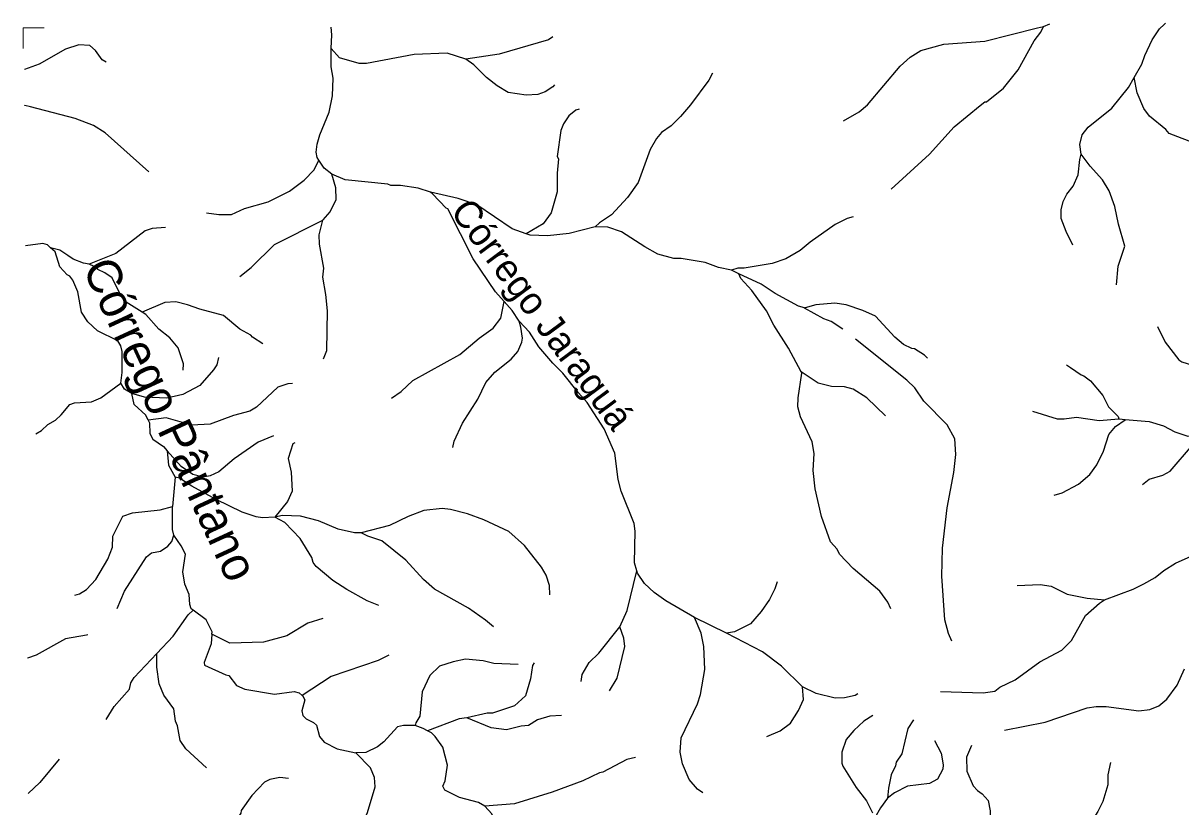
# Model space of a CAD drawing. Extents: x 393 to 446.6, y 8175.5 to 8231.
# Drawn here: x 392.99 to 399.75, y 8226.24 to 8230.82 of the extents above; entities that cross this region are included whole.
import ezdxf
from ezdxf.enums import TextEntityAlignment as Align

# ---------------------------------------------------------------- set-up
doc = ezdxf.new("R2010")
doc.units = 0
doc.header["$LTSCALE"] = 0.064
doc.linetypes.add('LONG_DASHED', pattern=[7.5, 6, -1.5])
doc.layers.add('61', color=7, linetype='Continuous')
for name, color, linetype, lineweight in [('63', 7, 'Continuous', 13), ('7', 7, 'Continuous', 25), ('9', 7, 'LONG_DASHED', 25)]:
    doc.layers.add(name, color=color, linetype=linetype, lineweight=lineweight)

msp = doc.modelspace()

# ---------------------------------------------------------------- linework, layer by layer
at = {"layer": '63'}
msp.add_lwpolyline([(393.1158, 8230.7899), (392.9926, 8230.7899), (392.9926, 8230.6685)], dxfattribs=at)
at = {"layer": '7'}
msp.add_line((398.9443, 8230.7981), (398.9812, 8230.814), dxfattribs=at)
for points in [[(397.7775, 8230.2468), (397.8682, 8230.2997), (397.9166, 8230.3401), (398.1087, 8230.5662), (398.1653, 8230.6178), (398.2283, 8230.6566), (398.3623, 8230.6953), (398.6013, 8230.7115), (398.9092, 8230.789), (398.9443, 8230.7981)], [(398.0551, 8229.8492), (398.2783, 8230.0527), (398.4236, 8230.2125), (398.5738, 8230.3369), (398.6013, 8230.3579), (398.611, 8230.3579), (398.7111, 8230.4386), (398.7966, 8230.5452), (398.8887, 8230.7132), (398.9288, 8230.7645), (398.9443, 8230.7981)], [(399.4726, 8230.5002), (399.5168, 8230.5775), (399.5346, 8230.6292), (399.5782, 8230.7196), (399.6202, 8230.7842), (399.6485, 8230.81), (399.6563, 8230.8171)], [(393.4765, 8230.5902), (393.4544, 8230.603), (393.4146, 8230.6566), (393.3807, 8230.6857), (393.3177, 8230.6905), (393.2402, 8230.6647), (393.0851, 8230.5781), (393.0006, 8230.5457), (393.0005, 8230.5457)], [(399.1639, 8230.0524), (399.1558, 8230.1082), (399.1697, 8230.1657), (399.2036, 8230.2109), (399.3425, 8230.3207), (399.4393, 8230.4419), (399.4726, 8230.5002)], [(399.9445, 8230.105), (399.8964, 8230.0995), (399.8447, 8230.1092), (399.6768, 8230.1722), (399.6573, 8230.1964), (399.5621, 8230.2739), (399.5282, 8230.3191), (399.491, 8230.4096), (399.4726, 8230.5002)], [(393.7252, 8229.9502), (393.4711, 8230.177), (393.4033, 8230.219), (393.2951, 8230.261), (393.0351, 8230.3288), (393.0016, 8230.3375), (393.0015, 8230.3376)], [(399.1152, 8229.5216), (399.076, 8229.6005), (399.047, 8229.6765), (399.047, 8229.7281), (399.0582, 8229.7766), (399.0808, 8229.8186), (399.1164, 8229.8654), (399.1454, 8229.9316), (399.1551, 8230.022), (399.1639, 8230.0524)], [(399.3697, 8229.2906), (399.3796, 8229.3987), (399.4184, 8229.515), (399.3812, 8229.6442), (399.3602, 8229.7475), (399.3263, 8229.8379), (399.2875, 8229.9025), (399.2165, 8229.9816), (399.1639, 8230.0524)], [(399.6087, 8229.0463), (399.6541, 8228.9563), (399.7333, 8228.8529), (399.751, 8228.8416), (399.9658, 8228.7737), (400.032, 8228.735), (400.1143, 8228.6575), (400.1998, 8228.622)], [(399.0775, 8228.824), (399.1009, 8228.8071), (399.1632, 8228.7641), (399.1786, 8228.7584), (399.2181, 8228.7302), (399.2892, 8228.6446), (399.3231, 8228.5784), (399.3796, 8228.5218), (399.3832, 8228.5077), (399.3833, 8228.5073)], [(398.8791, 8228.5536), (399.0237, 8228.5089), (399.0636, 8228.5073), (399.1368, 8228.5186), (399.2691, 8228.4992), (399.3833, 8228.5073)], [(399.0067, 8228.0623), (399.0533, 8228.0763), (399.1471, 8228.1262), (399.2149, 8228.1843), (399.2552, 8228.2393), (399.294, 8228.32), (399.3247, 8228.4169), (399.3634, 8228.4637), (399.4193, 8228.5031), (399.4211, 8228.5043)], [(399.3833, 8228.5073), (399.3848, 8228.5074), (399.4211, 8228.5043)], [(399.4211, 8228.5043), (399.5603, 8228.4926), (399.6438, 8228.4669), (399.7103, 8228.4325), (399.7866, 8228.4064), (399.8461, 8228.4127), (399.8464, 8228.4131)], [(399.5206, 8228.1256), (399.5605, 8228.1569), (399.6396, 8228.1795), (399.6832, 8228.2037), (399.8124, 8228.3539), (399.8458, 8228.412), (399.8464, 8228.4131)], [(399.2989, 8227.4527), (399.4668, 8227.5142), (399.5282, 8227.5449), (399.5944, 8227.582), (399.646, 8227.624), (399.7139, 8227.666), (399.8576, 8227.7306), (399.9642, 8227.7597), (400.2096, 8227.8016), (400.3647, 8227.8049), (400.5862, 8227.7858)], [(398.7908, 8227.5362), (398.9243, 8227.5417), (398.9888, 8227.532), (399.0825, 8227.4851), (399.1988, 8227.4609), (399.2989, 8227.4527)], [(398.3436, 8226.9177), (398.5916, 8226.9087), (398.6594, 8226.9183), (398.6885, 8226.9426), (398.7789, 8226.9862), (398.9226, 8227.0895), (399.0502, 8227.159), (399.1067, 8227.2155), (399.189, 8227.3608), (399.2698, 8227.4335), (399.2989, 8227.4527)], [(393.3697, 8227.247), (393.3614, 8227.2456), (393.2402, 8227.2252), (393.069, 8227.1283), (393.0173, 8227.1124), (393.0171, 8227.1123)], [(398.7159, 8226.6908), (398.9533, 8226.7375), (399.1988, 8226.8215), (399.2504, 8226.8295), (399.3086, 8226.8295), (399.4991, 8226.8037), (399.5637, 8226.8118), (399.617, 8226.8328), (399.6638, 8226.8715), (399.7235, 8226.9539), (399.7672, 8227.0491)], [(397.9481, 8226.7774), (397.8956, 8226.744), (397.8375, 8226.6891), (397.7939, 8226.6374), (397.768, 8226.5631), (397.768, 8226.4985), (397.7729, 8226.4824), (397.8504, 8226.3564), (397.9117, 8226.2789), (397.9459, 8226.2097)], [(398.1849, 8226.7511), (398.1524, 8226.702), (398.1168, 8226.5534), (398.0845, 8226.505), (398.0813, 8226.484), (398.0555, 8226.4307), (398.0393, 8226.3532), (398.0342, 8226.2953)], [(398.3074, 8226.6319), (398.3461, 8226.5567), (398.3591, 8226.4889), (398.3558, 8226.4646), (398.3251, 8226.4065), (398.2783, 8226.3806), (398.1508, 8226.3645), (398.0749, 8226.3257), (398.0342, 8226.2953)], [(398.5237, 8226.6023), (398.4947, 8226.5341), (398.4963, 8226.4533), (398.5334, 8226.3677), (398.5593, 8226.3386), (398.5868, 8226.3209), (398.6206, 8226.2805), (398.6336, 8226.2208), (398.6336, 8226.1336), (398.6513, 8226.1013), (398.6497, 8226.09), (398.6739, 8226.0657), (398.6917, 8226.0318), (398.6982, 8225.9915), (398.682, 8225.9382), (398.6546, 8225.9204), (398.6416, 8225.8849), (398.6449, 8225.8365), (398.6704, 8225.7237)], [(393.2019, 8226.5216), (393.09, 8226.3855), (393.0212, 8226.3227), (393.0209, 8226.3225)], [(399.3353, 8226.502), (399.3182, 8226.4307), (399.3182, 8226.3726), (399.2892, 8226.2757), (399.2617, 8226.2176), (399.2294, 8226.1691), (399.1987, 8226.14), (399.1203, 8226.0969)], [(394.5396, 8226.4097), (394.49, 8226.4162), (394.4319, 8226.4033), (394.4012, 8226.3887), (394.3269, 8226.3112), (394.2639, 8226.2224), (394.2623, 8226.2079), (394.2219, 8226.1465), (393.8893, 8225.9285), (393.8054, 8225.8946), (393.6826, 8225.8623), (393.4889, 8225.7912), (393.481, 8225.7868), (393.3177, 8225.6959), (393.237, 8225.6701), (393.181, 8225.6595), (393.1388, 8225.6505)], [(398.0342, 8226.2953), (397.9935, 8226.2378), (397.9601, 8226.1809)]]:
    msp.add_lwpolyline(points, dxfattribs=at)
at = {"layer": '9'}
for p, q in [((397.1668, 8229.3547), (397.1241, 8229.3749)), ((397.0954, 8227.2574), (396.9083, 8227.3483))]:
    msp.add_line(p, q, dxfattribs=at)
for points in [[(394.7892, 8230.6685), (394.7921, 8230.7491), (394.7899, 8230.7946)], [(396.0821, 8230.7369), (396.0566, 8230.7206), (395.7693, 8230.6353), (395.5744, 8230.6071)], [(394.7181, 8230.0169), (394.7079, 8230.0331), (394.7023, 8230.0642), (394.7075, 8230.1119), (394.7233, 8230.1661), (394.777, 8230.2972), (394.7969, 8230.3938), (394.8015, 8230.4967), (394.7887, 8230.5617), (394.7892, 8230.6685)], [(395.5744, 8230.6071), (395.465, 8230.6412), (395.2729, 8230.6341), (394.9959, 8230.581), (394.9525, 8230.5807), (394.8382, 8230.6141), (394.7892, 8230.6685)], [(396.0922, 8230.4576), (396.0829, 8230.4452), (396.0374, 8230.4154), (395.9937, 8230.4001), (395.9265, 8230.3966), (395.8219, 8230.4129), (395.7567, 8230.451), (395.6951, 8230.4995), (395.6208, 8230.5737), (395.5744, 8230.6071)], [(397.0134, 8230.5247), (396.9913, 8230.4839), (396.8848, 8230.3401), (396.8266, 8230.2723), (396.7717, 8230.2174), (396.7152, 8230.1786), (396.6861, 8230.1447), (396.649, 8230.0802), (396.5796, 8229.888), (396.5166, 8229.7992), (396.4245, 8229.699), (396.3535, 8229.6522), (396.3286, 8229.6288)], [(396.2348, 8230.3146), (396.2169, 8230.3095), (396.1755, 8230.2763), (396.1446, 8230.2304), (396.1288, 8230.1907), (396.1065, 8230.0386), (396.1145, 8230.0247), (396.1064, 8229.9413), (396.1079, 8229.8321), (396.0717, 8229.7108), (396.0266, 8229.6467), (395.9263, 8229.5878)], [(394.0617, 8229.7097), (394.1338, 8229.7005), (394.207, 8229.7015), (394.2828, 8229.7353), (394.4215, 8229.7749), (394.5455, 8229.8376), (394.6323, 8229.9001), (394.6894, 8229.9615), (394.7181, 8230.0169)], [(394.7921, 8229.9358), (394.7476, 8229.97), (394.7181, 8230.0169)], [(394.7401, 8229.6675), (394.7425, 8229.6687), (394.783, 8229.7158), (394.8182, 8229.7879), (394.817, 8229.8554), (394.7921, 8229.9358)], [(395.3693, 8229.8311), (395.296, 8229.854), (395.1934, 8229.8701), (395.1372, 8229.8702), (395.1197, 8229.8766), (394.8705, 8229.9027), (394.7921, 8229.9358)], [(395.7986, 8229.1929), (395.7483, 8229.2494), (395.6166, 8229.4418), (395.4694, 8229.7336), (395.4592, 8229.7383), (395.3804, 8229.8212), (395.3693, 8229.8311)], [(395.9263, 8229.5878), (395.8441, 8229.6171), (395.6379, 8229.757), (395.5307, 8229.7939), (395.3693, 8229.8311)], [(393.8236, 8229.6249), (393.745, 8229.6194), (393.7041, 8229.6053), (393.534, 8229.473), (393.3782, 8229.4112)], [(394.2571, 8229.3379), (394.3229, 8229.3914), (394.4593, 8229.526), (394.7401, 8229.6675)], [(394.7441, 8228.8575), (394.7639, 8228.9074), (394.7674, 8229.1382), (394.7587, 8229.2331), (394.7396, 8229.335), (394.7472, 8229.3869), (394.7215, 8229.5278), (394.7196, 8229.5814), (394.74, 8229.6671), (394.7401, 8229.6675)], [(396.3286, 8229.6288), (396.1765, 8229.5892), (396.0505, 8229.5764), (395.9489, 8229.5798), (395.9263, 8229.5878)], [(397.1241, 8229.3749), (397.0481, 8229.3912), (396.9703, 8229.4195), (396.8309, 8229.4438), (396.7869, 8229.4442), (396.6951, 8229.4699), (396.6181, 8229.5112), (396.4816, 8229.5995), (396.4019, 8229.6262), (396.3286, 8229.6288)], [(397.834, 8229.6871), (397.7988, 8229.678), (397.7281, 8229.6427), (397.5825, 8229.5393), (397.5252, 8229.4903), (397.4404, 8229.4409), (397.3604, 8229.4147), (397.1972, 8229.3876), (397.1603, 8229.3872), (397.1241, 8229.3749)], [(393.1529, 8229.5062), (393.1341, 8229.5228), (393.1076, 8229.5322), (393.0056, 8229.5185), (393.0055, 8229.5184)], [(393.3782, 8229.4112), (393.345, 8229.4172), (393.2844, 8229.4399), (393.2524, 8229.462), (393.2066, 8229.4922), (393.1529, 8229.5062)], [(393.5627, 8228.7159), (393.5695, 8228.7792), (393.5696, 8228.9007), (393.5614, 8228.9336), (393.5448, 8228.9641), (393.426, 8229.0212), (393.3689, 8229.0748), (393.3323, 8229.1307), (393.3109, 8229.2488), (393.282, 8229.3177), (393.2657, 8229.3404), (393.2498, 8229.3487), (393.2067, 8229.395), (393.1789, 8229.4831), (393.1529, 8229.5062)], [(393.687, 8229.1308), (393.5939, 8229.1888), (393.5646, 8229.2246), (393.5109, 8229.3312), (393.4683, 8229.361), (393.4283, 8229.38), (393.4062, 8229.3972), (393.3782, 8229.4112)], [(397.5503, 8229.1548), (397.5493, 8229.1554), (397.5157, 8229.1661), (397.3791, 8229.2396), (397.2963, 8229.2936), (397.1668, 8229.3547)], [(397.5307, 8228.7828), (397.4573, 8228.9199), (397.3701, 8229.0543), (397.3274, 8229.1378), (397.2425, 8229.2566), (397.1791, 8229.3269), (397.1668, 8229.3547)], [(394.3904, 8228.9463), (394.3303, 8228.9841), (394.3199, 8228.9966), (394.2565, 8229.0312), (394.1609, 8229.1108), (394.0225, 8229.1481), (393.9514, 8229.1743), (393.8822, 8229.1903), (393.8186, 8229.1876), (393.687, 8229.1308)], [(395.1405, 8228.6288), (395.1982, 8228.6679), (395.2659, 8228.7322), (395.54, 8228.8839), (395.6526, 8228.9787), (395.7339, 8229.0378), (395.7778, 8229.0955), (395.7986, 8229.1929)], [(395.8852, 8229.0788), (395.8452, 8229.1406), (395.7986, 8229.1929)], [(398.2666, 8228.8617), (398.2492, 8228.8803), (398.1911, 8228.9175), (398.175, 8228.9191), (398.1281, 8228.9417), (398.0765, 8228.9853), (397.9634, 8229.1064), (397.8908, 8229.1403), (397.7939, 8229.1742), (397.7261, 8229.1823), (397.6163, 8229.1742), (397.5529, 8229.1556), (397.5503, 8229.1548)], [(398.4089, 8227.211), (398.3889, 8227.2566), (398.3687, 8227.3355), (398.3509, 8227.5899), (398.354, 8227.7534), (398.3817, 8227.9888), (398.4203, 8228.1958), (398.4332, 8228.2999), (398.4268, 8228.3921), (398.3816, 8228.4733), (398.2456, 8228.6122), (398.1938, 8228.6883), (398.1459, 8228.7333), (397.7743, 8229.032), (397.7049, 8229.0754), (397.6625, 8229.0912), (397.5503, 8229.1548)], [(393.9268, 8228.7913), (393.9277, 8228.8282), (393.8966, 8228.923), (393.8487, 8228.9803), (393.7844, 8229.0321), (393.7082, 8229.1176), (393.687, 8229.1308)], [(395.4978, 8228.3401), (395.5073, 8228.378), (395.5543, 8228.4832), (395.6444, 8228.6236), (395.6914, 8228.7204), (395.7432, 8228.7803), (395.8398, 8228.8561), (395.8773, 8228.9005), (395.9011, 8228.9561), (395.9045, 8228.9788), (395.8963, 8229.0435), (395.8852, 8229.0788)], [(396.5718, 8227.6214), (396.5593, 8227.6679), (396.5618, 8227.8522), (396.5568, 8227.8968), (396.4812, 8228.0869), (396.4633, 8228.1552), (396.443, 8228.3075), (396.3818, 8228.4505), (396.2823, 8228.6041), (396.2311, 8228.659), (396.1402, 8228.7753), (396.0827, 8228.8328), (396.0007, 8228.9293), (395.9464, 8229.0143), (395.8852, 8229.0788)], [(394.1328, 8228.8669), (394.1217, 8228.8239), (394.1036, 8228.7943), (394.0237, 8228.7023), (393.9231, 8228.6497), (393.8304, 8228.6286), (393.7006, 8228.6356), (393.6271, 8228.6565)], [(398.0539, 8227.4005), (398.0364, 8227.4377), (397.9895, 8227.5023), (397.8331, 8227.6346), (397.7539, 8227.7187), (397.7402, 8227.7479), (397.701, 8227.7905), (397.6495, 8227.9375), (397.6115, 8228.0997), (397.6001, 8228.2069), (397.6065, 8228.305), (397.5953, 8228.3742), (397.5261, 8228.5193), (397.5112, 8228.5788), (397.5129, 8228.6313), (397.5338, 8228.7749), (397.5307, 8228.7828)], [(398.0232, 8228.5253), (397.9137, 8228.6313), (397.8343, 8228.6816), (397.7833, 8228.6959), (397.7077, 8228.6962), (397.6294, 8228.7165), (397.5307, 8228.7828)], [(393.0672, 8228.4212), (393.1004, 8228.4404), (393.1374, 8228.4759), (393.1807, 8228.5013), (393.215, 8228.5316), (393.2645, 8228.5909), (393.2925, 8228.6012), (393.3904, 8228.6082), (393.4466, 8228.6298), (393.5627, 8228.7159)], [(393.6271, 8228.6565), (393.5832, 8228.6812), (393.5627, 8228.7159)], [(394.564, 8228.7137), (394.5355, 8228.712), (394.4786, 8228.6923), (394.3527, 8228.5763), (394.3143, 8228.5539), (394.2194, 8228.5283), (394.0839, 8228.4765), (393.9774, 8228.4708), (393.8262, 8228.5136), (393.7216, 8228.5003)], [(393.7216, 8228.5003), (393.7076, 8228.5294), (393.6404, 8228.5911), (393.6271, 8228.6565)], [(393.7216, 8228.5003), (393.7287, 8228.4854), (393.732, 8228.4226), (393.7494, 8228.3899), (393.812, 8228.3467), (393.8321, 8228.3206)], [(394.4525, 8228.4096), (394.3635, 8228.3712), (394.2226, 8228.274), (394.1331, 8228.1996), (394.0841, 8228.1766), (394.0417, 8228.1685), (393.9816, 8228.1827), (393.9133, 8228.2307), (393.8321, 8228.3206)], [(394.5774, 8228.3685), (394.5654, 8228.3618), (394.5385, 8228.2772), (394.5561, 8228.1979), (394.5608, 8228.0869), (394.5342, 8228.0256), (394.4604, 8227.9345)], [(393.8321, 8228.3206), (393.8404, 8228.2381), (393.8783, 8228.1684)], [(393.8783, 8228.1684), (393.8786, 8228.1678), (393.8634, 8227.996)], [(394.4604, 8227.9345), (394.3888, 8227.9308), (394.3513, 8227.9355), (394.2704, 8227.9631), (394.1186, 8228.0374), (393.9765, 8228.1149), (393.9041, 8228.1627), (393.8783, 8228.1684)], [(393.2945, 8227.4801), (393.3213, 8227.4864), (393.3618, 8227.5131), (393.4166, 8227.5698), (393.487, 8227.6886), (393.5144, 8227.76), (393.5151, 8227.8235), (393.5749, 8227.9404), (393.6309, 8227.9597), (393.792, 8227.9766), (393.8634, 8227.996)], [(393.8718, 8227.8296), (393.8636, 8227.8631), (393.8634, 8227.996)], [(394.9638, 8227.8434), (394.925, 8227.844), (394.8302, 8227.8639), (394.7145, 8227.9131), (394.6095, 8227.9405), (394.5046, 8227.9437), (394.4604, 8227.9345)], [(395.0665, 8227.4185), (394.9989, 8227.4453), (394.8801, 8227.5119), (394.7988, 8227.5655), (394.7025, 8227.6471), (394.6838, 8227.6709), (394.6758, 8227.6993), (394.6083, 8227.8106), (394.5194, 8227.9029), (394.4604, 8227.9345)], [(396.065, 8227.4809), (396.0628, 8227.5352), (396.0434, 8227.5966), (396.016, 8227.6434), (395.9159, 8227.7694), (395.8254, 8227.8501), (395.6801, 8227.9195), (395.5849, 8227.9534), (395.4847, 8227.9793), (395.4363, 8227.9841), (395.3297, 8227.9728), (395.2377, 8227.9389), (395.1295, 8227.8856), (394.9638, 8227.8434)], [(393.54, 8227.4012), (393.5838, 8227.5036), (393.7113, 8227.7023), (393.7413, 8227.7273), (393.7934, 8227.737), (393.8368, 8227.7656), (393.86, 8227.7921), (393.8718, 8227.8296)], [(393.9833, 8227.3914), (393.9734, 8227.3987), (393.9646, 8227.4254), (393.9603, 8227.4827), (393.936, 8227.5435), (393.9233, 8227.6151), (393.939, 8227.7177), (393.9147, 8227.7667), (393.8718, 8227.8296)], [(395.7355, 8227.2936), (395.6895, 8227.3342), (395.5902, 8227.4035), (395.3927, 8227.5142), (395.3271, 8227.5699), (395.224, 8227.6827), (395.0849, 8227.7954), (395.003, 8227.8228), (394.9638, 8227.8434)], [(396.4737, 8227.2936), (396.5161, 8227.3905), (396.5718, 8227.6214)], [(396.9083, 8227.3483), (396.7419, 8227.4469), (396.6736, 8227.4954), (396.6161, 8227.5472), (396.5756, 8227.6072), (396.5718, 8227.6214)], [(397.3912, 8227.5569), (397.3777, 8227.5167), (397.3453, 8227.4543), (397.2962, 8227.3836), (397.234, 8227.3115), (397.1414, 8227.2656), (397.0954, 8227.2574)], [(393.7716, 8227.1384), (393.8679, 8227.2405), (393.9546, 8227.3654), (393.9833, 8227.3914)], [(394.0934, 8227.2517), (394.0943, 8227.2646), (394.0607, 8227.3347), (393.9833, 8227.3914)], [(394.7399, 8227.343), (394.6534, 8227.3156), (394.5307, 8227.2415), (394.3942, 8227.2043), (394.1979, 8227.1996), (394.0934, 8227.2517)], [(396.9572, 8226.3254), (396.9252, 8226.348), (396.877, 8226.4028), (396.8382, 8226.4947), (396.825, 8226.5636), (396.8296, 8226.6474), (396.9265, 8226.8456), (396.9429, 8226.8995), (396.9686, 8227.0465), (396.963, 8227.1792), (396.9464, 8227.2579), (396.9083, 8227.3483)], [(396.2482, 8226.9764), (396.2539, 8227.0164), (396.2948, 8227.087), (396.3504, 8227.1403), (396.4737, 8227.2936)], [(396.4134, 8226.9219), (396.4567, 8226.9958), (396.5019, 8227.1792), (396.497, 8227.2289), (396.4737, 8227.2936)], [(394.0934, 8227.2517), (394.0893, 8227.196), (394.0479, 8227.0871), (394.0505, 8227.0712), (394.1739, 8227.0135), (394.1926, 8227.0101), (394.2364, 8226.9526), (394.2851, 8226.9307), (394.4583, 8226.9022), (394.5734, 8226.9166), (394.602, 8226.9091), (394.6206, 8226.8938)], [(397.5377, 8226.9446), (397.4148, 8227.0647), (397.3043, 8227.1483), (397.0954, 8227.2574)], [(393.4771, 8226.7533), (393.5241, 8226.8297), (393.6122, 8226.9302), (393.6199, 8226.9684), (393.6394, 8226.9984), (393.7716, 8227.1384)], [(394.0612, 8226.4725), (393.9414, 8226.5836), (393.9084, 8226.6315), (393.8924, 8226.7174), (393.8811, 8226.7446), (393.8713, 8226.8166), (393.8138, 8226.8955), (393.786, 8226.9621), (393.7714, 8227.0593), (393.7716, 8227.1384)], [(395.1264, 8227.129), (395.0631, 8227.0985), (394.7894, 8227.0041), (394.6207, 8226.8939), (394.6206, 8226.8938)], [(395.8805, 8227.075), (395.7381, 8227.08), (395.6754, 8227.0958), (395.5724, 8227.1057), (395.5002, 8227.0908), (395.4203, 8227.0651), (395.364, 8227.0108), (395.32, 8226.9145), (395.3068, 8226.7726), (395.2822, 8226.7339), (395.2796, 8226.7188)], [(395.9733, 8227.0847), (395.9637, 8227.0695), (395.9526, 8226.9914), (395.9224, 8226.8918), (395.858, 8226.8339), (395.7297, 8226.7912), (395.6999, 8226.7904), (395.5807, 8226.764)], [(397.331, 8226.6555), (397.408, 8226.6883), (397.4674, 8226.7329), (397.5141, 8226.8065), (397.5433, 8226.8709), (397.5377, 8226.9446)], [(397.8601, 8226.9037), (397.8448, 8226.8946), (397.7827, 8226.8802), (397.7281, 8226.8781), (397.6181, 8226.9063), (397.5377, 8226.9446)], [(394.6206, 8226.8938), (394.6213, 8226.8932), (394.635, 8226.8687), (394.6171, 8226.8051), (394.6243, 8226.7781), (394.6437, 8226.7569), (394.6868, 8226.7364), (394.7039, 8226.7214), (394.7208, 8226.6545), (394.7489, 8226.6222), (394.825, 8226.582), (394.9328, 8226.5589)], [(395.2796, 8226.7188), (395.2108, 8226.7196), (395.1769, 8226.7116), (395.0968, 8226.6242), (395.0597, 8226.5952), (394.9904, 8226.5619), (394.9328, 8226.5589)], [(395.5807, 8226.764), (395.5354, 8226.7572), (395.3502, 8226.6883)], [(396.1334, 8226.7778), (396.064, 8226.7729), (395.9934, 8226.7518), (395.9394, 8226.7182), (395.8964, 8226.7155), (395.8125, 8226.6939), (395.722, 8226.7053), (395.5807, 8226.764)], [(395.3502, 8226.6883), (395.3261, 8226.7011), (395.2796, 8226.7188)], [(395.6848, 8226.2481), (395.6485, 8226.2687), (395.5379, 8226.2984), (395.4525, 8226.3406), (395.4412, 8226.3644), (395.4538, 8226.3951), (395.467, 8226.4882), (395.4397, 8226.5916), (395.3957, 8226.6548), (395.3744, 8226.6756), (395.3502, 8226.6883)], [(394.981, 8226.1677), (395.0001, 8226.2115), (395.0452, 8226.3606), (395.0419, 8226.4152), (395.019, 8226.4716), (394.9328, 8226.5589)], [(396.5641, 8226.533), (396.5136, 8226.5204), (396.3728, 8226.4469), (396.3542, 8226.4431), (396.2575, 8226.395), (396.0778, 8226.3295), (395.8587, 8226.2627), (395.6848, 8226.2481)], [(395.8202, 8226.0522), (395.7668, 8226.0997), (395.7267, 8226.2036), (395.6848, 8226.2481)]]:
    msp.add_lwpolyline(points, dxfattribs=at)

# ---------------------------------------------------------------- texts
at = {"layer": '61'}
for s, height, rotation, p in [('Córrego Jaraguá', 0.16, 306.554, (395.957, 8229.0717)), ('Córrego Pântano', 0.2, 294.775, (393.7631, 8228.4644))]:
    msp.add_text(s, height=height, rotation=rotation, dxfattribs=at).set_placement(p, align=Align.CENTER)

doc.saveas('drawing.dxf')
